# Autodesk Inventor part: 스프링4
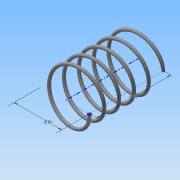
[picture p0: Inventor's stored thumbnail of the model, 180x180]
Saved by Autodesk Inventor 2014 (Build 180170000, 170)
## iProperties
Created: 2015-06
Part Number: 스프링4
Material: 강철, 연강
Document SubType Name: Modeling
Designer: MYHOME
Density: 7.86 g/cm^3
Appearance: 강철
Mass: 1.52988 g
Surface Area: 7.87024 cm^2
Volume: 0.194641 cm^3
Author: MYHOME
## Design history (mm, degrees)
sketch "스케치1"
  geometry: L1 (0, 0)-(8, 0); L2 (8, 0)-(8, 14.5); L3 (8, 14.5)-(0, 14.5); L4 (0, 14.5)-(0, 0); C1 r 0.5 at (8, 0)
  constraints: 8 end point, 2 parallel, 1 centre point, 1 coincident, 1 horizontal, 1 perpendicular
  dimensions: "d0" = 16 diameter of L2 L4; "d1" = 14.5 distance of L1.end L2.end (derived); "d2" = 1 diameter of C1
feature "코일2" sketch "스케치1" pitch "d17" = 10; turns "d19" = 5; dims "d18" = 14.5 (= d1), "d20" = 0, angle "d21" = 90 deg, angle "d22" = 90 deg, "d23" = 0, "d24" = 0
node "작업 평면3"
sketch "스케치4"
  geometry: L1 (-8.5, 0)-(-7.5, 0) reference; 1 further point
  constraints: 1 horizontal alignment
extrude "돌출3" cut sketch "스케치4" stored distance "d26" = 10; taper "d27" = 0 deg
node "작업 평면4"
sketch "스케치5"
  geometry: L1 (-7.5, 0)-(-8.5, 0) reference; 1 further point
  constraints: 1 horizontal alignment
extrude "돌출4" cut sketch "스케치5" stored distance "d29" = 10; taper "d30" = 0 deg
node "솔리드2"
node "절단 모서리 투영3"
node "절단 모서리 투영4"
other parameters: "d25" = 0, "d28" = 14.5 (= d1)
